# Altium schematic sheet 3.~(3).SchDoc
size 420 x 297 mm
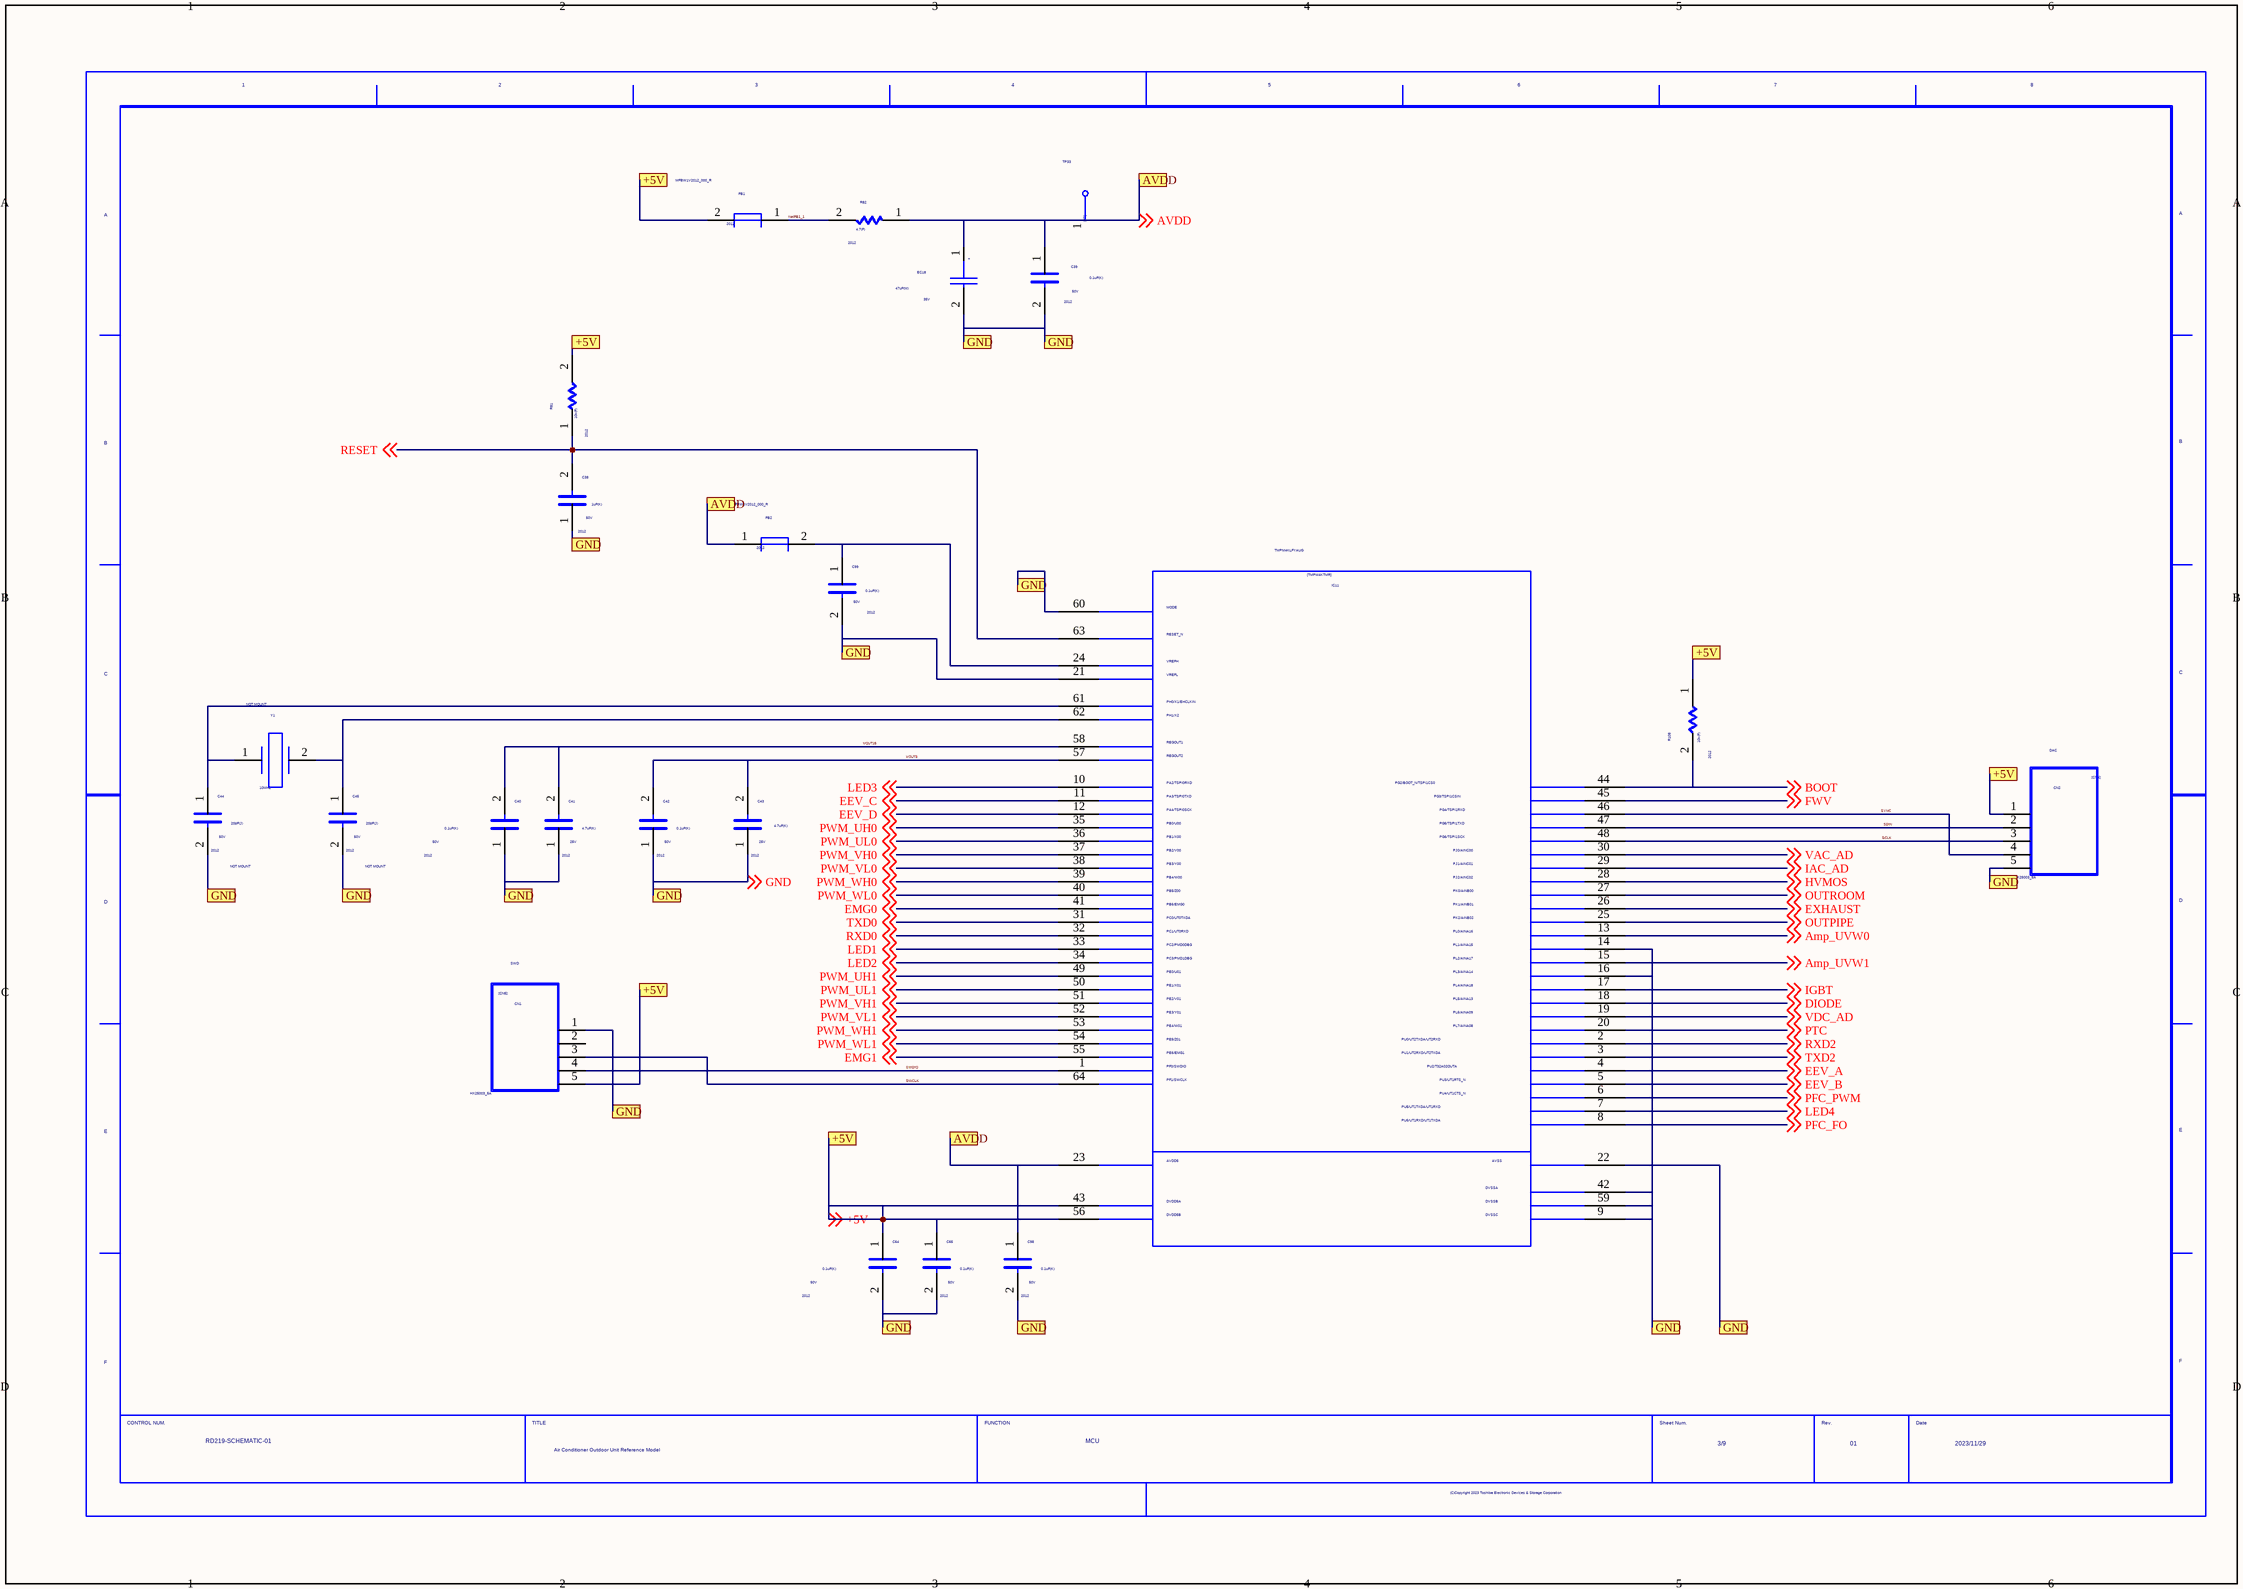
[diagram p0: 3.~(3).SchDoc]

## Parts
C38  SIZECODESMD: 2012  VAL2: 50V  VAL1: 1uF(K)  (hidden comment: C)
C39  SIZECODESMD: 2012  VAL2: 50V  VAL1: 0.1uF(K)  (hidden comment: C)
C40  SIZECODESMD: 2012  VAL2: 50V  VAL1: 0.1uF(K)  (hidden comment: C)
C41  SIZECODESMD: 2012  VAL2: 25V  VAL1: 4.7uF(K)  (hidden comment: C)
C42  SIZECODESMD: 2012  VAL2: 50V  VAL1: 0.1uF(K)  (hidden comment: C)
C43  SIZECODESMD: 2012  VAL2: 25V  VAL1: 4.7uF(K)  (hidden comment: C)
C44  NOTMOUNT: NOT MOUNT  SIZECODESMD: 2012  VAL2: 50V  VAL1: 20pF(J)  (hidden comment: C)
C45  NOTMOUNT: NOT MOUNT  SIZECODESMD: 2012  VAL2: 50V  VAL1: 20pF(J)  (hidden comment: C)
C64  SIZECODESMD: 2012  VAL2: 50V  VAL1: 0.1uF(K)  (hidden comment: C)
C65  SIZECODESMD: 2012  VAL2: 50V  VAL1: 0.1uF(K)  (hidden comment: C)
C98  SIZECODESMD: 2012  VAL2: 50V  VAL1: 0.1uF(K)  (hidden comment: C)
C99  SIZECODESMD: 2012  VAL2: 50V  VAL1: 0.1uF(K)  (hidden comment: C)
CN1  VAL3: HX25003_5A  COMPCOMMENT: SWD  (hidden comment: CN5)
CN2  VAL3: HX25003_5A  COMPCOMMENT: DAC  (hidden comment: CN5)
EC18  VAL2: 35V  VAL1: 47uF(M)  (hidden comment: EC)
FB1  SIZECODESMD: 2012  VAL3: MFBW1V2012_000_R  (hidden comment: FL08A)
FB2  SIZECODESMD: 2012  VAL3: MFBW1V2012_000_R  (hidden comment: FL08A)
IC11  TMPM4KLFYAUG
R81  SIZECODESMD: 2012  VAL1: 10k(F)  (hidden comment: R)
R82  SIZECODESMD: 2012  VAL1: 4.7(F)  (hidden comment: R)
R108  SIZECODESMD: 2012  VAL1: 10k(F)  (hidden comment: R)
TP33  TP  (value not drawn)
U?  DATE: 2023/11/29  TITLE: Air Conditioner Outdoor Unit / Reference Model  DRAWINGNUMBER: RD219-SCHEMATIC-01  SHEETNUMBER: 3/9  REVISION: 01  FUNCTION: MCU  (hidden comment: WAKU_DEF100)
Y1  NOTMOUNT: NOT MOUNT  VAL1: 10MHz  (hidden comment: X)

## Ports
+5V, AVDD, GND

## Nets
+5V: C64.1 C65.1 CN1.5 CN2.1 FB1.2 IC11.43 IC11.56 R81.2 R108.1 ; off-sheet +5V, port +5V
Amp_UVW0: IC11.13 ; off-sheet Amp_UVW0
Amp_UVW1: IC11.15 ; off-sheet Amp_UVW1
AVDD: C39.1 C98.1 EC18.1 FB2.1 IC11.23 R82.1 TP33.1 ; off-sheet AVDD, port AVDD
BOOT: IC11.44 R108.2 ; off-sheet BOOT
DIODE: IC11.18 ; off-sheet DIODE
EEV_A: IC11.4 ; off-sheet EEV_A
EEV_B: IC11.5 ; off-sheet EEV_B
EEV_C: IC11.11 ; off-sheet EEV_C
EEV_D: IC11.12 ; off-sheet EEV_D
EMG0: IC11.41 ; off-sheet EMG0
EMG1: IC11.55 ; off-sheet EMG1
EXHAUST: IC11.26 ; off-sheet EXHAUST
FWV: IC11.45 ; off-sheet FWV
GND: C38.1 C39.2 C40.1 C41.1 C42.1 C43.1 C44.2 C45.2 C64.2 C65.2 C98.2 C99.2 CN1.1 CN2.5 EC18.2 IC11.9 IC11.14 IC11.16 IC11.21 IC11.22 IC11.42 IC11.59 IC11.60 ; off-sheet GND, port GND
HVMOS: IC11.28 ; off-sheet HVMOS
IAC_AD: IC11.29 ; off-sheet IAC_AD
IGBT: IC11.17 ; off-sheet IGBT
LED1: IC11.33 ; off-sheet LED1
LED2: IC11.34 ; off-sheet LED2
LED3: IC11.10 ; off-sheet LED3
LED4: IC11.7 ; off-sheet LED4
NetC99_1: C99.1 FB2.2 IC11.24
NetFB1_1: FB1.1 R82.2
OUTPIPE: IC11.25 ; off-sheet OUTPIPE
OUTROOM: IC11.27 ; off-sheet OUTROOM
PFC_FO: IC11.8 ; off-sheet PFC_FO
PFC_PWM: IC11.6 ; off-sheet PFC_PWM
PTC: IC11.20 ; off-sheet PTC
PWM_UH0: IC11.35 ; off-sheet PWM_UH0
PWM_UH1: IC11.49 ; off-sheet PWM_UH1
PWM_UL0: IC11.36 ; off-sheet PWM_UL0
PWM_UL1: IC11.50 ; off-sheet PWM_UL1
PWM_VH0: IC11.37 ; off-sheet PWM_VH0
PWM_VH1: IC11.51 ; off-sheet PWM_VH1
PWM_VL0: IC11.38 ; off-sheet PWM_VL0
PWM_VL1: IC11.52 ; off-sheet PWM_VL1
PWM_WH0: IC11.39 ; off-sheet PWM_WH0
PWM_WH1: IC11.53 ; off-sheet PWM_WH1
PWM_WL0: IC11.40 ; off-sheet PWM_WL0
PWM_WL1: IC11.54 ; off-sheet PWM_WL1
RESET: C38.2 IC11.63 R81.1 ; off-sheet RESET
RXD0: IC11.32 ; off-sheet RXD0
RXD2: IC11.2 ; off-sheet RXD2
SCLK: CN2.3 IC11.48
SDIN: CN2.2 IC11.47
SWCLK: CN1.3 IC11.64
SWDIO: CN1.4 IC11.1
SYNC: CN2.4 IC11.46
TXD0: IC11.31 ; off-sheet TXD0
TXD2: IC11.3 ; off-sheet TXD2
VAC_AD: IC11.30 ; off-sheet VAC_AD
VDC_AD: IC11.19 ; off-sheet VDC_AD
VOUT3: C42.2 C43.2 IC11.57
VOUT15: C40.2 C41.2 IC11.58
X1: C44.1 IC11.61 Y1.1
X2: C45.1 IC11.62 Y1.2

Not connected (* = marked no-connect by the designer): CN1 2

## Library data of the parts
C38 = C: OriginalSymbolOrigin: (2540,7620); VAL3: AC0805KKX7R9BB105
C39 C40 C42 C64 C65 C98 C99 = C: OriginalSymbolOrigin: (2540,7620); VAL3: AC0805KRX7R9BB104
C41 = C: OriginalSymbolOrigin: (2540,7620); COMP: AC0805KKX7R8BB475
C43 = C: OriginalSymbolOrigin: (2540,7620); VAL3: AC0805KKX7R8BB475
C44 = C: OriginalSymbolOrigin: (2540,7620); VAL3: AC0805JRNPO9BN200
C45 = C: OriginalSymbolOrigin: (2540,7620); COMP: AC0805JRNPO9BN200
CN1 CN2 = CN5: OriginalSymbolOrigin: (2540,22860)
EC18 = EC: SAVEAREA0: -1432,-1528,20311,14389; SAVECOUNT: 53; TIME: 15:02:55; UPDATEUSER: w20165dm; UPDATETIME: 16:35:05; OriginalSymbolOrigin: (2540,10160); VAL3: ESY476M035AE3AA; COMP: 35V47UF_6.3X7
FB1 = FL08A: SAVEAREA0: -112,-1299,15373,8886; TIME: 08:53:27; UPDATEUSER: kishi-s; UPDATETIME: 15:03:21; SAVECOUNT: 4; OriginalSymbolOrigin: (5080,5080); VAL2: 3A; VAL1: 0ohm
FB2 = FL08A_Dup1: SAVEAREA0: -112,-1299,15373,8886; TIME: 08:53:27; UPDATEUSER: kishi-s; UPDATETIME: 15:03:21; SAVECOUNT: 4; OriginalSymbolOrigin: (5080,5080); VAL2: 3A; VAL1: 0ohm
IC11 = TMPM4KLFYAUG: SAVEAREA0: -81909,-1350,188872,133365; TIME: 14:58:35; UPDATEUSER: w20165dm; UPDATETIME: 11:11:19; SAVECOUNT: 16; OriginalSymbolOrigin: (7620,129540); USERCOMPTEXT3: TOSHIBA
R81 = R: OriginalSymbolOrigin: (5080,5080); VAL2: 125mW; VAL3: AC0805FR-0710KL; COMP: AC08005FR_0710KL
R82 = R: OriginalSymbolOrigin: (5080,5080); VAL2: 125mW; VAL3: AC0805FR-074R7L; COMP: AC0805FR_074R7L
R108 = R: OriginalSymbolOrigin: (5080,5080); VAL3: AC0805FR_0710KL; VAL2: 125mW; COMP: AC08005FR_0710KL
TP33 = TP_Dup1: TIME: 16:12:21; UPDATEUSER: fukuda-y; UPDATETIME: 16:18:11; SAVECOUNT: 2; SAVEAREA0: -242,-92,12810,7836; OriginalSymbolOrigin: (0,7620); VAL3: ZXD; COMPCOMMENT: AVDD
U? = WAKU_DEF100: PLOTTIME: HH:MM; SAVEAREA0: -45080,-4508,463680,304612; TIME: 18:05:21; UPDATEUSER: sptcae13; UPDATETIME: 08:19:30; SAVECOUNT: 8; OriginalSymbolOrigin: (10160,284480)
Y1 = X: SAVEAREA0: -5556,-184,20536,15665; TIME: 10:12:32; UPDATEUSER: fukuda-y; SAVECOUNT: 1; OriginalSymbolOrigin: (0,10160); VAL3: NX5032GA_10MHZ_STD_CSK_7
